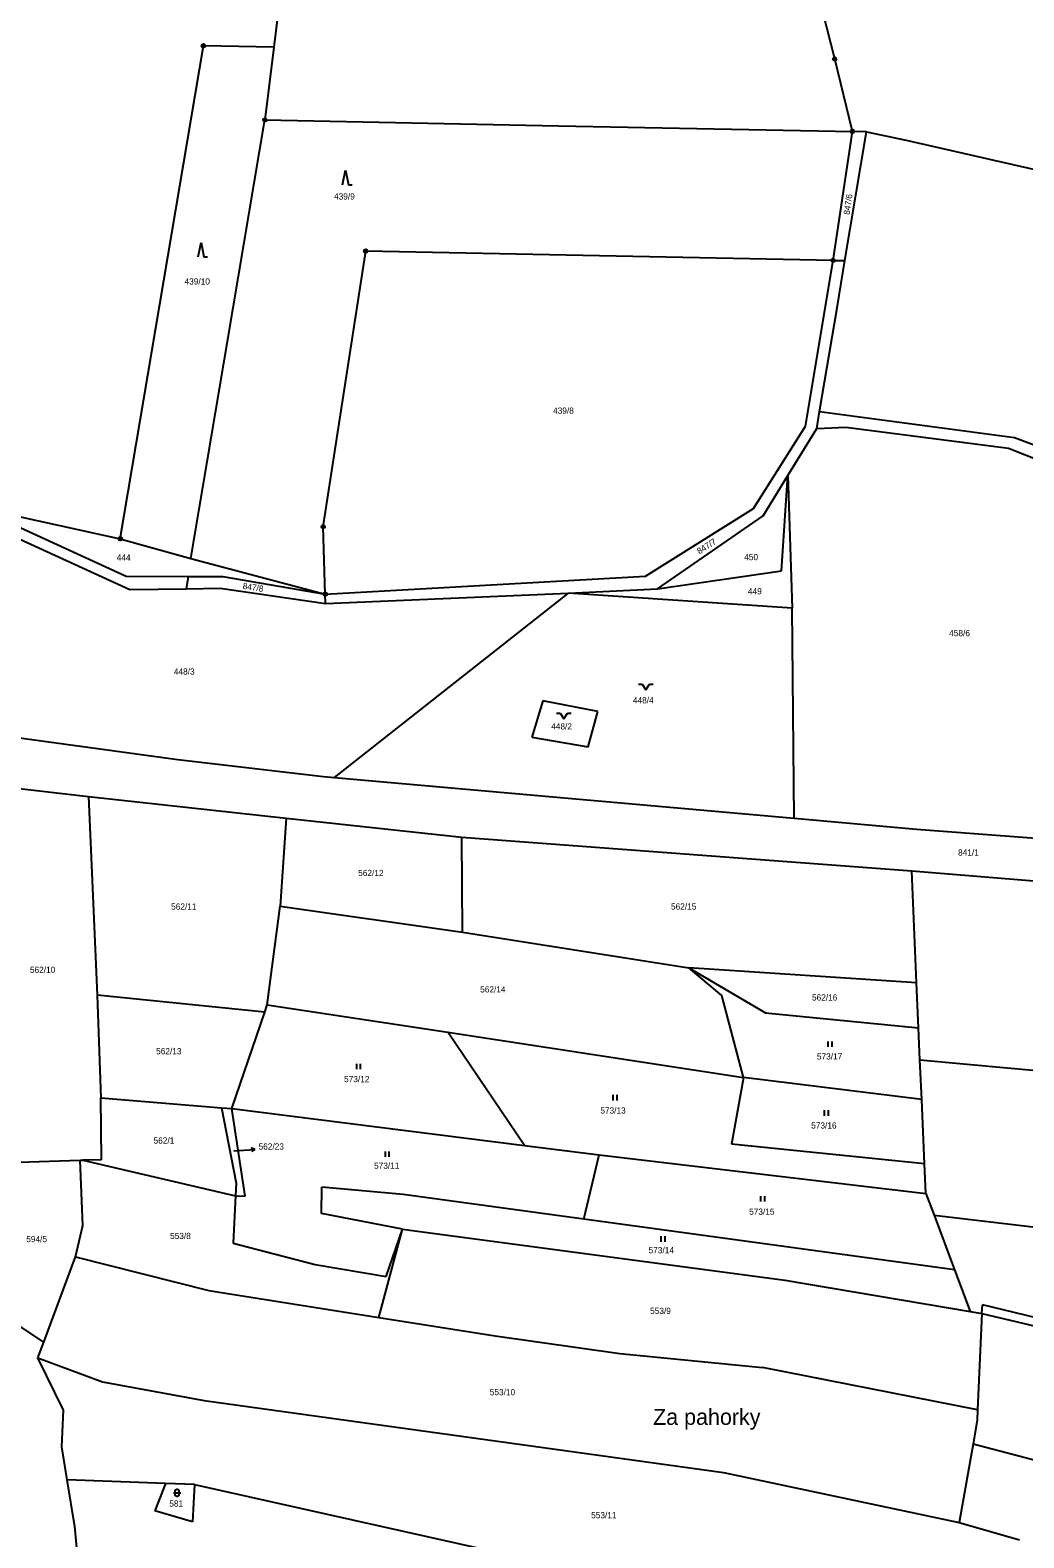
# Model space of a CAD drawing. Extents: x -791032 to -787751, y -1106872 to -1104403.
# Drawn here: x -788932.6 to -788660.3, y -1105436.1 to -1105023 of the extents above; entities that cross this region are included whole.
import ezdxf

# ---------------------------------------------------------------- set-up
doc = ezdxf.new("R2010")
doc.units = 0
for name, color, linetype in [('Komunikace', 7, 'Continuous'), ('Vrstva 1', 7, 'Continuous'), ('Vrstva 14', 7, 'Continuous'), ('Vrstva 16', 7, 'Continuous'), ('Vrstva 23', 7, 'Continuous'), ('Vrstva 28', 7, 'Continuous'), ('Vrstva 39', 7, 'Continuous')]:
    doc.layers.add(name, color=color, linetype=linetype)

msp = doc.modelspace()

# ---------------------------------------------------------------- linework, layer by layer
at = {"layer": 'Komunikace'}
msp.add_line((-788876.85, -1105330.09), (-788874.04, -1105329.93), dxfattribs=at)
at = {"layer": 'Vrstva 1'}
for p, q in [((-788712.14, -1105030.91), (-788716.96, -1105011.61)), ((-788907.93, -1105162.37), (-788885.16, -1105027.28)), ((-788865.86, -1105027.68), (-788885.16, -1105027.28)), ((-788865.86, -1105027.68), (-788868.31, -1105047.62)), ((-788707.3, -1105050.75), (-788712.14, -1105030.91)), ((-788878.44, -1105107.77), (-788868.31, -1105047.62)), ((-788868.31, -1105047.62), (-788787.8, -1105049.19)), ((-788787.8, -1105049.19), (-788707.3, -1105050.75)), ((-788712.58, -1105086.09), (-788707.3, -1105050.75)), ((-788709.34, -1105086.15), (-788703.43, -1105050.9)), ((-788703.43, -1105050.9), (-788707.3, -1105050.75)), ((-788703.43, -1105050.9), (-788692.57, -1105053.12)), ((-788692.57, -1105053.12), (-788610.93, -1105071.73)), ((-788852.33, -1105159.07), (-788840.68, -1105083.55)), ((-788712.58, -1105086.09), (-788840.68, -1105083.55)), ((-788720.18, -1105131.55), (-788712.58, -1105086.09)), ((-788712.58, -1105086.09), (-788709.34, -1105086.15)), ((-788711.5, -1105099.09), (-788709.34, -1105086.15)), ((-788716.26, -1105127.52), (-788711.5, -1105099.09)), ((-788888.56, -1105167.81), (-788878.44, -1105107.77)), ((-788717.03, -1105132.13), (-788716.26, -1105127.52)), ((-788716.26, -1105127.52), (-788662.87, -1105134.6)), ((-788734.37, -1105154.09), (-788720.18, -1105131.55)), ((-788724.96, -1105145.06), (-788717.03, -1105132.13)), ((-788717.03, -1105132.13), (-788709.12, -1105131.77)), ((-788709.12, -1105131.77), (-788664.49, -1105137.54)), ((-788662.87, -1105134.6), (-788648.7, -1105139.98)), ((-788664.49, -1105137.54), (-788650.65, -1105143.07)), ((-788731.72, -1105156.09), (-788724.96, -1105145.06)), ((-788726.73, -1105171.17), (-788724.96, -1105145.06)), ((-788724.96, -1105145.06), (-788723.76, -1105181.42)), ((-788947.63, -1105153.68), (-788907.93, -1105162.37)), ((-788947.63, -1105153.68), (-788906.32, -1105172.61)), ((-788764.01, -1105172.63), (-788734.37, -1105154.09)), ((-788760.66, -1105176.13), (-788731.72, -1105156.09)), ((-788851.74, -1105177.53), (-788852.33, -1105159.07)), ((-788935.69, -1105162.36), (-788905.31, -1105176.29)), ((-788907.93, -1105162.37), (-788888.56, -1105167.81)), ((-788888.56, -1105167.81), (-788851.74, -1105177.53)), ((-788906.32, -1105172.61), (-788889.27, -1105172.68)), ((-788889.77, -1105176.07), (-788889.27, -1105172.68)), ((-788889.27, -1105172.68), (-788879.81, -1105172.72)), ((-788879.81, -1105172.72), (-788851.74, -1105177.53)), ((-788851.74, -1105177.53), (-788764.01, -1105172.63)), ((-788760.66, -1105176.13), (-788726.73, -1105171.17)), ((-788905.31, -1105176.29), (-788889.77, -1105176.07)), ((-788889.77, -1105176.07), (-788880.59, -1105175.94)), ((-788880.59, -1105175.94), (-788851.66, -1105180.14)), ((-788851.66, -1105180.14), (-788851.74, -1105177.53)), ((-788851.66, -1105180.14), (-788785.12, -1105177.31)), ((-788849.26, -1105227.77), (-788785.12, -1105177.31)), ((-788785.12, -1105177.31), (-788760.66, -1105176.13)), ((-788723.76, -1105181.42), (-788785.12, -1105177.31)), ((-788723.24, -1105238.96), (-788723.76, -1105181.42)), ((-788792.12, -1105206.82), (-788795.11, -1105216.7)), ((-788777.07, -1105209.7), (-788792.12, -1105206.82)), ((-788779.7, -1105219.35), (-788777.07, -1105209.7)), ((-788940.81, -1105216.19), (-788892.13, -1105222.86)), ((-788795.11, -1105216.7), (-788779.7, -1105219.35)), ((-788892.13, -1105222.86), (-788852.24, -1105227.51)), ((-788852.24, -1105227.51), (-788849.26, -1105227.77)), ((-788942.24, -1105230.09), (-788916.68, -1105232.99)), ((-788849.26, -1105227.77), (-788723.24, -1105238.96)), ((-788916.68, -1105232.99), (-788914.26, -1105287.48)), ((-788916.68, -1105232.99), (-788862.45, -1105238.9)), ((-788862.45, -1105238.9), (-788864.1, -1105263.09)), ((-788862.45, -1105238.9), (-788814.31, -1105244.15)), ((-788723.24, -1105238.96), (-788689.76, -1105241.93)), ((-788689.76, -1105241.93), (-788630.76, -1105246.44)), ((-788814.15, -1105270.21), (-788814.31, -1105244.15)), ((-788814.31, -1105244.15), (-788691.02, -1105253.38)), ((-788691.02, -1105253.38), (-788635.53, -1105257.92)), ((-788689.7, -1105284.07), (-788691.02, -1105253.38)), ((-788867.64, -1105290.1), (-788864.1, -1105263.09)), ((-788864.1, -1105263.09), (-788814.15, -1105270.21)), ((-788814.15, -1105270.21), (-788752.1, -1105279.99)), ((-788689.7, -1105284.07), (-788752.1, -1105279.99)), ((-788752.1, -1105279.99), (-788731.11, -1105292.26)), ((-788743.04, -1105287.54), (-788752.1, -1105279.99)), ((-788689.16, -1105296.36), (-788689.7, -1105284.07)), ((-788914.26, -1105287.48), (-788913.28, -1105315.62)), ((-788868.34, -1105292.13), (-788914.26, -1105287.48)), ((-788737.12, -1105309.96), (-788743.04, -1105287.54)), ((-788877.4, -1105318.5), (-788868.34, -1105292.13)), ((-788868.34, -1105292.13), (-788867.64, -1105290.1)), ((-788867.64, -1105290.1), (-788818.2, -1105297.62)), ((-788731.11, -1105292.26), (-788689.16, -1105296.36)), ((-788818.2, -1105297.62), (-788737.12, -1105309.96)), ((-788797.19, -1105328.65), (-788818.2, -1105297.62)), ((-788688.77, -1105305.14), (-788689.16, -1105296.36)), ((-788688.29, -1105316), (-788688.77, -1105305.14)), ((-788688.77, -1105305.14), (-788623.41, -1105311.16)), ((-788737.12, -1105309.96), (-788740.45, -1105328.3)), ((-788688.29, -1105316), (-788737.12, -1105309.96)), ((-788913.28, -1105315.62), (-788880.18, -1105318.28)), ((-788913.09, -1105332.52), (-788913.28, -1105315.62)), ((-788880.18, -1105318.28), (-788876.15, -1105338.96)), ((-788880.18, -1105318.28), (-788877.4, -1105318.5)), ((-788687.51, -1105333.67), (-788688.29, -1105316)), ((-788873.73, -1105342.49), (-788877.4, -1105318.5)), ((-788877.4, -1105318.5), (-788797.19, -1105328.65)), ((-788797.19, -1105328.65), (-788776.73, -1105331.24)), ((-788687.51, -1105333.67), (-788740.45, -1105328.3)), ((-788935.87, -1105333.19), (-788918.93, -1105332.67)), ((-788918.93, -1105332.67), (-788918.17, -1105332.65)), ((-788918.19, -1105350.57), (-788918.93, -1105332.67)), ((-788913.09, -1105332.52), (-788918.17, -1105332.65)), ((-788918.17, -1105332.65), (-788876.33, -1105342.43)), ((-788780.9, -1105348.81), (-788776.73, -1105331.24)), ((-788776.73, -1105331.24), (-788687.15, -1105341.8)), ((-788687.15, -1105341.8), (-788687.51, -1105333.67)), ((-788876.15, -1105338.96), (-788876.33, -1105342.43)), ((-788876.33, -1105342.43), (-788876.99, -1105355.4)), ((-788876.33, -1105342.43), (-788873.73, -1105342.49)), ((-788852.8, -1105347.28), (-788852.7, -1105340.05)), ((-788830.37, -1105342.05), (-788852.7, -1105340.05)), ((-788780.9, -1105348.81), (-788830.37, -1105342.05)), ((-788687.15, -1105341.8), (-788684.91, -1105347.77)), ((-788830.57, -1105351.6), (-788852.8, -1105347.28)), ((-788920.18, -1105359.13), (-788918.19, -1105350.57)), ((-788679.32, -1105362.68), (-788780.9, -1105348.81)), ((-788684.91, -1105347.77), (-788620.64, -1105355.36)), ((-788684.91, -1105347.77), (-788679.32, -1105362.68)), ((-788876.99, -1105355.4), (-788854.53, -1105361.27)), ((-788837.12, -1105375.76), (-788830.57, -1105351.6)), ((-788835.1, -1105364.52), (-788830.57, -1105351.6)), ((-788830.57, -1105351.6), (-788725.83, -1105365.54)), ((-788928.91, -1105382.54), (-788920.18, -1105359.13)), ((-788920.18, -1105359.13), (-788883.69, -1105368.37)), ((-788854.53, -1105361.27), (-788835.1, -1105364.52)), ((-788679.32, -1105362.68), (-788675.01, -1105374.16)), ((-788725.83, -1105365.54), (-788675.01, -1105374.16)), ((-788883.69, -1105368.37), (-788837.12, -1105375.76)), ((-788928.91, -1105382.54), (-788942.31, -1105373.67)), ((-788837.12, -1105375.76), (-788805.16, -1105380.83)), ((-788675.01, -1105374.16), (-788671.78, -1105374.71)), ((-788671.78, -1105374.71), (-788672.97, -1105401.05)), ((-788671.78, -1105374.71), (-788671.67, -1105372.32)), ((-788671.78, -1105374.71), (-788578.13, -1105396.85)), ((-788622, -1105384.31), (-788671.67, -1105372.32)), ((-788930.5, -1105386.8), (-788928.91, -1105382.54)), ((-788805.16, -1105380.83), (-788771.02, -1105385.66)), ((-788930.5, -1105386.8), (-788912.84, -1105393.44)), ((-788923.46, -1105401.17), (-788930.5, -1105386.8)), ((-788771.02, -1105385.66), (-788731.94, -1105389.43)), ((-788672.97, -1105401.05), (-788731.94, -1105389.43)), ((-788912.84, -1105393.44), (-788884.98, -1105398.55)), ((-788884.98, -1105398.55), (-788742.65, -1105418.27)), ((-788672.97, -1105401.05), (-788673.1, -1105403.92)), ((-788923.94, -1105411.21), (-788923.46, -1105401.17)), ((-788673.1, -1105403.92), (-788674.22, -1105410.35)), ((-788922.47, -1105420.21), (-788923.94, -1105411.21)), ((-788674.22, -1105410.35), (-788677.98, -1105431.96)), ((-788674.22, -1105410.35), (-788578.44, -1105435.57)), ((-788920.38, -1105433.02), (-788922.47, -1105420.21)), ((-788895.56, -1105421.22), (-788922.47, -1105420.21)), ((-788895.56, -1105421.22), (-788898.5, -1105428.76)), ((-788887.6, -1105421.52), (-788895.56, -1105421.22)), ((-788887.6, -1105421.52), (-788888.17, -1105431.74)), ((-788887.6, -1105421.52), (-788729.96, -1105456.71)), ((-788742.65, -1105418.27), (-788677.98, -1105431.96)), ((-788888.17, -1105431.74), (-788898.5, -1105428.76)), ((-788918.91, -1105449.1), (-788920.38, -1105433.02)), ((-788677.98, -1105431.96), (-788661.51, -1105436.73))]:
    msp.add_line(p, q, dxfattribs=at)
msp.add_lwpolyline([(-788717.46, -1104999.27), (-788859.07, -1104972.5), (-788865.86, -1105027.68)], dxfattribs=at)
at = {"layer": 'Vrstva 16'}
for p, q in [((-788874.04, -1105329.93), (-788871.044, -1105329.759)), ((-788871.044, -1105329.759), (-788872.071, -1105329.317)), ((-788871.044, -1105329.759), (-788872.014, -1105330.315))]:
    msp.add_line(p, q, dxfattribs=at)
at = {"layer": 'Vrstva 23'}
for p, q in [((-788847, -1105065.36), (-788846.2, -1105061.36)), ((-788846.2, -1105061.36), (-788845.4, -1105065.36)), ((-788845.4, -1105065.36), (-788844.4, -1105065.36)), ((-788886.61, -1105085.16), (-788885.81, -1105081.16)), ((-788885.81, -1105081.16), (-788885.01, -1105085.16)), ((-788885.01, -1105085.16), (-788884.01, -1105085.16)), ((-788765.91, -1105202.25), (-788764.91, -1105202.25)), ((-788764.91, -1105202.25), (-788763.91, -1105203.75)), ((-788763.91, -1105203.75), (-788762.91, -1105202.25)), ((-788762.91, -1105202.25), (-788761.91, -1105202.25)), ((-788788.36, -1105210.2), (-788787.36, -1105210.2)), ((-788787.36, -1105210.2), (-788786.36, -1105211.7)), ((-788786.36, -1105211.7), (-788785.36, -1105210.2)), ((-788785.36, -1105210.2), (-788784.36, -1105210.2)), ((-788713.91, -1105301.64), (-788713.91, -1105300.14)), ((-788712.91, -1105300.14), (-788712.91, -1105301.64)), ((-788843.15, -1105307.76), (-788843.15, -1105306.26)), ((-788842.15, -1105306.26), (-788842.15, -1105307.76)), ((-788772.89, -1105316.29), (-788772.89, -1105314.79)), ((-788771.89, -1105314.79), (-788771.89, -1105316.29)), ((-788714.97, -1105320.48), (-788714.97, -1105318.98)), ((-788713.97, -1105318.98), (-788713.97, -1105320.48)), ((-788835.29, -1105331.75), (-788835.29, -1105330.25)), ((-788834.29, -1105330.25), (-788834.29, -1105331.75)), ((-788732.34, -1105344.01), (-788732.34, -1105342.51)), ((-788731.34, -1105342.51), (-788731.34, -1105344.01)), ((-788759.71, -1105355.01), (-788759.71, -1105353.51)), ((-788758.71, -1105353.51), (-788758.71, -1105355.01)), ((-788893.36, -1105423.82), (-788891.36, -1105423.82)), ((-788892.86, -1105423.22), (-788892.76, -1105423.02)), ((-788892.86, -1105424.42), (-788892.86, -1105423.22)), ((-788892.76, -1105424.62), (-788892.86, -1105424.42)), ((-788892.76, -1105423.02), (-788892.66, -1105422.92)), ((-788892.66, -1105424.72), (-788892.76, -1105424.62)), ((-788892.66, -1105422.92), (-788892.46, -1105422.82)), ((-788892.46, -1105424.82), (-788892.66, -1105424.72)), ((-788892.46, -1105422.82), (-788892.26, -1105422.82)), ((-788892.26, -1105424.82), (-788892.46, -1105424.82)), ((-788892.26, -1105422.82), (-788892.06, -1105422.92)), ((-788892.06, -1105424.72), (-788892.26, -1105424.82)), ((-788892.06, -1105422.92), (-788891.96, -1105423.02)), ((-788891.96, -1105424.62), (-788892.06, -1105424.72)), ((-788891.96, -1105423.02), (-788891.86, -1105423.22)), ((-788891.86, -1105424.42), (-788891.96, -1105424.62)), ((-788891.86, -1105423.22), (-788891.86, -1105424.42))]:
    msp.add_line(p, q, dxfattribs=at)
at = {"layer": 'Vrstva 28'}
for centre, radius in [((-788885.16, -1105027.28), 0.5), ((-788885.16, -1105027.28), 0.01), ((-788712.14, -1105030.91), 0.5), ((-788712.14, -1105030.91), 0.01), ((-788868.31, -1105047.62), 0.5), ((-788868.31, -1105047.62), 0.01), ((-788707.3, -1105050.75), 0.5), ((-788707.3, -1105050.75), 0.01), ((-788840.68, -1105083.55), 0.5), ((-788840.68, -1105083.55), 0.01), ((-788712.58, -1105086.09), 0.5), ((-788712.58, -1105086.09), 0.01), ((-788852.33, -1105159.07), 0.5), ((-788852.33, -1105159.07), 0.01), ((-788907.93, -1105162.37), 0.5), ((-788907.93, -1105162.37), 0.01), ((-788851.74, -1105177.53), 0.5), ((-788851.74, -1105177.53), 0.01)]:
    msp.add_circle(centre, radius, dxfattribs=at)

# ---------------------------------------------------------------- texts
at = {"layer": 'Vrstva 14'}
for s, height, p in [('439/9', 1.7, (-788849.356, -1105069.42)), ('439/10', 1.7, (-788890.318, -1105092.71)), ('439/8', 1.7, (-788789.316, -1105128.12)), ('444', 1.7, (-788908.914, -1105168.38)), ('450', 1.7, (-788736.938, -1105168.25)), ('449', 1.7, (-788735.918, -1105177.59)), ('458/6', 1.7, (-788680.762, -1105189.08)), ('448/3', 1.7, (-788893.251, -1105199.61)), ('448/4', 1.7, (-788767.447, -1105207.48)), ('448/2', 1.7, (-788789.841, -1105214.63)), ('562/12', 1.7, (-788842.739, -1105254.81)), ('562/11', 1.7, (-788894.002, -1105264.02)), ('562/15', 1.7, (-788757.006, -1105263.99)), ('562/10', 1.7, (-788932.698, -1105281.33)), ('562/14', 1.7, (-788809.305, -1105286.7)), ('562/16', 1.7, (-788718.359, -1105288.91)), ('562/13', 1.7, (-788898.109, -1105303.65)), ('573/17', 1.7, (-788717.013, -1105305.07)), ('573/12', 1.7, (-788846.596, -1105311.29)), ('573/13', 1.7, (-788776.366, -1105319.89)), ('573/16', 1.7, (-788718.576, -1105323.99)), ('562/1', 1.7, (-788898.819, -1105328.12)), ('562/23', 0.1, (-788877.1, -1105330.09)), ('573/11', 1.7, (-788838.389, -1105335.02)), ('573/15', 1.7, (-788735.592, -1105347.61)), ('594/5', 1.7, (-788933.698, -1105355.13)), ('553/8', 1.7, (-788894.292, -1105354.28)), ('573/14', 1.7, (-788763.152, -1105358.17)), ('553/9', 1.7, (-788762.723, -1105374.81)), ('553/10', 1.7, (-788806.665, -1105397.07)), ('581', 1.7, (-788894.506, -1105427.59)), ('553/11', 1.7, (-788778.879, -1105430.78))]:
    msp.add_text(s, height=height, dxfattribs=at).set_placement(p)
for s, rotation, p in [('847/6', 82.15848, (-788708.04, -1105073.679)), ('847/7', 32.84199, (-788749.2, -1105166.69)), ('847/8', 351.05634, (-788874.479, -1105176.075))]:
    msp.add_text(s, height=1.7, rotation=rotation, dxfattribs=at).set_placement(p)
at = {"layer": 'Vrstva 16'}
for s, p in [('841/1', (-788678.322, -1105249.19)), ('562/23', (-788870.04, -1105329.76))]:
    msp.add_text(s, height=1.7, dxfattribs=at).set_placement(p)
at = {"layer": 'Vrstva 39'}
msp.add_text('Za pahorky', height=4.4, dxfattribs=at).set_placement((-788761.91, -1105405.2))

doc.saveas('drawing.dxf')
